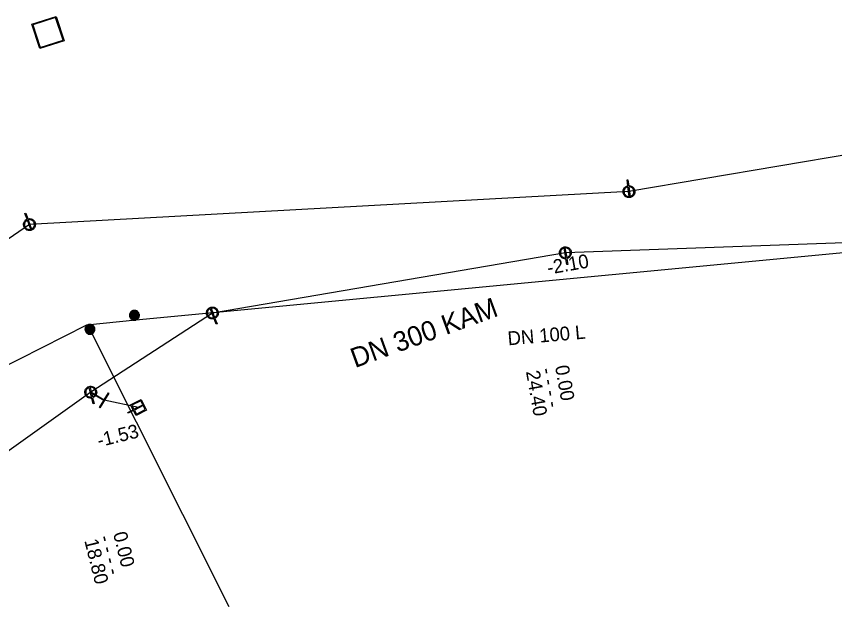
# Model space of a CAD drawing. Extents: x -818321 to -817653, y -1049725 to -1049329.
# Drawn here: x -817798.86 to -817757.35, y -1049402.58 to -1049372.62 of the extents above; entities that cross this region are included whole.
import ezdxf

# ---------------------------------------------------------------- set-up
doc = ezdxf.new("R2010")
doc.units = 0
doc.layers.add('Default', color=7, linetype='Continuous')
doc.layers.add('Level 0', color=7, linetype='Continuous')

msp = doc.modelspace()

# ---------------------------------------------------------------- linework, layer by layer
at = {"layer": 'Default'}
for points in [[(-817798.076, -1049373.026), (-817796.84, -1049372.624), (-817796.438, -1049373.86), (-817797.675, -1049374.262), (-817798.076, -1049373.026)], [(-817797.649, -1049374.211), (-817796.489, -1049373.834), (-817796.866, -1049372.675), (-817798.025, -1049373.052), (-817797.649, -1049374.211)], [(-817767.848, -1049381.223), (-817767.885, -1049380.925), (-817767.836, -1049380.919), (-817767.799, -1049381.217)], [(-817767.781, -1049381.767), (-817767.842, -1049381.274)], [(-817767.793, -1049381.268), (-817767.733, -1049381.761)], [(-817798.319, -1049382.917), (-817798.422, -1049382.635), (-817798.375, -1049382.618), (-817798.272, -1049382.9)], [(-817798.255, -1049382.948), (-817798.085, -1049383.415)], [(-817798.131, -1049383.432), (-817798.301, -1049382.965)], [(-817770.994, -1049384.872), (-817771.08, -1049384.382)], [(-817771.032, -1049384.373), (-817770.946, -1049384.863)], [(-817770.937, -1049384.913), (-817770.884, -1049385.209), (-817770.933, -1049385.218), (-817770.985, -1049384.922)], [(-817788.851, -1049387.918), (-817789.029, -1049387.453)], [(-817788.983, -1049387.436), (-817788.805, -1049387.9)], [(-817788.787, -1049387.948), (-817788.679, -1049388.228), (-817788.725, -1049388.246), (-817788.833, -1049387.965)], [(-817795.05, -1049391.944), (-817795.17, -1049391.461)], [(-817795.123, -1049391.449), (-817795.002, -1049391.932)], [(-817795.086, -1049391.706), (-817795.068, -1049391.696), (-817794.41, -1049392.091), (-817794.193, -1049391.727), (-817794.167, -1049391.743), (-817794.619, -1049392.496), (-817794.645, -1049392.48), (-817794.426, -1049392.116), (-817795.074, -1049391.728), (-817795.086, -1049391.706)], [(-817794.99, -1049391.982), (-817794.917, -1049392.273), (-817794.965, -1049392.285), (-817795.038, -1049391.993)], [(-817792.914, -1049392.629), (-817793.182, -1049392.765), (-817793.204, -1049392.721), (-817792.937, -1049392.585), (-817793.062, -1049392.34), (-817792.527, -1049392.067), (-817792.255, -1049392.602), (-817792.789, -1049392.874), (-817792.914, -1049392.629)], [(-817792.893, -1049392.563), (-817792.446, -1049392.335), (-817792.549, -1049392.134), (-817792.996, -1049392.361), (-817792.893, -1049392.563)], [(-817792.871, -1049392.607), (-817792.768, -1049392.808), (-817792.321, -1049392.581), (-817792.424, -1049392.379), (-817792.871, -1049392.607)]]:
    msp.add_lwpolyline(points, dxfattribs=at)
for points in [[(-817767.799, -1049381.217), (-817767.737, -1049381.213), (-817767.671, -1049381.241), (-817767.595, -1049381.271), (-817767.547, -1049381.337), (-817767.499, -1049381.403), (-817767.49, -1049381.481), (-817767.48, -1049381.559), (-817767.511, -1049381.635), (-817767.543, -1049381.711), (-817767.609, -1049381.759), (-817767.675, -1049381.806), (-817767.751, -1049381.815), (-817767.826, -1049381.824), (-817767.902, -1049381.795), (-817767.978, -1049381.765), (-817768.027, -1049381.698), (-817768.076, -1049381.632), (-817768.085, -1049381.554), (-817768.095, -1049381.476), (-817768.064, -1049381.401), (-817768.034, -1049381.325), (-817767.967, -1049381.277), (-817767.909, -1049381.235), (-817767.848, -1049381.223)], [(-817767.842, -1049381.274), (-817767.89, -1049381.283), (-817767.938, -1049381.318), (-817767.993, -1049381.358), (-817768.018, -1049381.42), (-817768.044, -1049381.483), (-817768.036, -1049381.548), (-817768.028, -1049381.612), (-817767.987, -1049381.668), (-817767.946, -1049381.723), (-817767.883, -1049381.748), (-817767.829, -1049381.769), (-817767.781, -1049381.767)], [(-817767.733, -1049381.761), (-817767.686, -1049381.751), (-817767.638, -1049381.718), (-817767.583, -1049381.679), (-817767.557, -1049381.615), (-817767.531, -1049381.551), (-817767.539, -1049381.487), (-817767.547, -1049381.422), (-817767.587, -1049381.367), (-817767.627, -1049381.313), (-817767.69, -1049381.287), (-817767.744, -1049381.265), (-817767.793, -1049381.268)], [(-817798.272, -1049382.9), (-817798.213, -1049382.883), (-817798.142, -1049382.894), (-817798.061, -1049382.907), (-817798, -1049382.96), (-817797.938, -1049383.014), (-817797.911, -1049383.087), (-817797.884, -1049383.161), (-817797.898, -1049383.243), (-817797.911, -1049383.324), (-817797.965, -1049383.385), (-817798.019, -1049383.446), (-817798.091, -1049383.472), (-817798.162, -1049383.498), (-817798.242, -1049383.486), (-817798.323, -1049383.474), (-817798.386, -1049383.42), (-817798.448, -1049383.366), (-817798.475, -1049383.293), (-817798.502, -1049383.219), (-817798.489, -1049383.139), (-817798.476, -1049383.058), (-817798.423, -1049382.997), (-817798.376, -1049382.942), (-817798.319, -1049382.917)], [(-817798.085, -1049383.415), (-817798.042, -1049383.395), (-817798.003, -1049383.352), (-817797.958, -1049383.301), (-817797.947, -1049383.233), (-817797.936, -1049383.165), (-817797.958, -1049383.104), (-817797.98, -1049383.043), (-817798.031, -1049382.999), (-817798.083, -1049382.954), (-817798.15, -1049382.944), (-817798.208, -1049382.935), (-817798.255, -1049382.948)], [(-817798.301, -1049382.965), (-817798.346, -1049382.985), (-817798.385, -1049383.03), (-817798.429, -1049383.081), (-817798.44, -1049383.148), (-817798.451, -1049383.214), (-817798.428, -1049383.275), (-817798.406, -1049383.337), (-817798.354, -1049383.382), (-817798.302, -1049383.426), (-817798.234, -1049383.436), (-817798.177, -1049383.445), (-817798.131, -1049383.432)], [(-817770.985, -1049384.922), (-817771.047, -1049384.929), (-817771.115, -1049384.905), (-817771.192, -1049384.879), (-817771.243, -1049384.815), (-817771.295, -1049384.752), (-817771.308, -1049384.675), (-817771.322, -1049384.598), (-817771.295, -1049384.52), (-817771.267, -1049384.442), (-817771.204, -1049384.391), (-817771.14, -1049384.341), (-817771.065, -1049384.327), (-817770.991, -1049384.314), (-817770.913, -1049384.34), (-817770.836, -1049384.366), (-817770.783, -1049384.429), (-817770.731, -1049384.493), (-817770.717, -1049384.571), (-817770.704, -1049384.648), (-817770.73, -1049384.725), (-817770.757, -1049384.802), (-817770.821, -1049384.853), (-817770.876, -1049384.899), (-817770.937, -1049384.913)], [(-817771.08, -1049384.382), (-817771.126, -1049384.394), (-817771.172, -1049384.43), (-817771.226, -1049384.472), (-817771.248, -1049384.537), (-817771.271, -1049384.602), (-817771.259, -1049384.666), (-817771.248, -1049384.73), (-817771.205, -1049384.783), (-817771.163, -1049384.836), (-817771.098, -1049384.857), (-817771.043, -1049384.877), (-817770.994, -1049384.872)], [(-817770.946, -1049384.863), (-817770.898, -1049384.851), (-817770.852, -1049384.814), (-817770.799, -1049384.771), (-817770.777, -1049384.707), (-817770.755, -1049384.643), (-817770.767, -1049384.579), (-817770.778, -1049384.515), (-817770.821, -1049384.462), (-817770.865, -1049384.409), (-817770.929, -1049384.387), (-817770.984, -1049384.369), (-817771.032, -1049384.373)], [(-817788.833, -1049387.965), (-817788.892, -1049387.984), (-817788.963, -1049387.974), (-817789.044, -1049387.963), (-817789.106, -1049387.91), (-817789.169, -1049387.857), (-817789.197, -1049387.785), (-817789.225, -1049387.711), (-817789.213, -1049387.63), (-817789.201, -1049387.548), (-817789.148, -1049387.486), (-817789.095, -1049387.424), (-817789.024, -1049387.397), (-817788.954, -1049387.37), (-817788.873, -1049387.38), (-817788.792, -1049387.391), (-817788.729, -1049387.444), (-817788.665, -1049387.496), (-817788.637, -1049387.57), (-817788.609, -1049387.642), (-817788.62, -1049387.723), (-817788.631, -1049387.804), (-817788.684, -1049387.866), (-817788.73, -1049387.922), (-817788.787, -1049387.948)], [(-817789.029, -1049387.453), (-817789.072, -1049387.474), (-817789.11, -1049387.518), (-817789.154, -1049387.57), (-817789.164, -1049387.638), (-817789.174, -1049387.706), (-817789.15, -1049387.767), (-817789.127, -1049387.828), (-817789.075, -1049387.871), (-817789.023, -1049387.914), (-817788.956, -1049387.924), (-817788.898, -1049387.932), (-817788.851, -1049387.918)], [(-817788.805, -1049387.9), (-817788.76, -1049387.879), (-817788.722, -1049387.834), (-817788.679, -1049387.782), (-817788.669, -1049387.715), (-817788.66, -1049387.648), (-817788.683, -1049387.587), (-817788.707, -1049387.527), (-817788.76, -1049387.483), (-817788.813, -1049387.439), (-817788.88, -1049387.43), (-817788.937, -1049387.423), (-817788.983, -1049387.436)], [(-817792.872, -1049387.543), (-817792.809, -1049387.543), (-817792.749, -1049387.575), (-817792.689, -1049387.607), (-817792.655, -1049387.668), (-817792.621, -1049387.728), (-817792.621, -1049387.793), (-817792.621, -1049387.858), (-817792.654, -1049387.918), (-817792.687, -1049387.977), (-817792.747, -1049388.01), (-817792.806, -1049388.043), (-817792.872, -1049388.043), (-817792.936, -1049388.043), (-817792.996, -1049388.01), (-817793.055, -1049387.977), (-817793.088, -1049387.918), (-817793.121, -1049387.858), (-817793.121, -1049387.793), (-817793.121, -1049387.728), (-817793.088, -1049387.668), (-817793.054, -1049387.607), (-817792.995, -1049387.575), (-817792.935, -1049387.543), (-817792.872, -1049387.543)], [(-817792.872, -1049387.566), (-817792.929, -1049387.566), (-817792.983, -1049387.596), (-817793.037, -1049387.625), (-817793.068, -1049387.679), (-817793.098, -1049387.734), (-817793.098, -1049387.793), (-817793.098, -1049387.852), (-817793.068, -1049387.906), (-817793.038, -1049387.96), (-817792.984, -1049387.99), (-817792.93, -1049388.019), (-817792.872, -1049388.019), (-817792.813, -1049388.019), (-817792.758, -1049387.99), (-817792.704, -1049387.96), (-817792.675, -1049387.906), (-817792.645, -1049387.852), (-817792.645, -1049387.793), (-817792.645, -1049387.734), (-817792.676, -1049387.679), (-817792.706, -1049387.625), (-817792.76, -1049387.596), (-817792.814, -1049387.566), (-817792.872, -1049387.566)], [(-817792.872, -1049387.583), (-817792.819, -1049387.583), (-817792.769, -1049387.61), (-817792.719, -1049387.637), (-817792.69, -1049387.688), (-817792.662, -1049387.738), (-817792.662, -1049387.793), (-817792.662, -1049387.848), (-817792.689, -1049387.897), (-817792.717, -1049387.947), (-817792.767, -1049387.975), (-817792.817, -1049388.002), (-817792.872, -1049388.002), (-817792.926, -1049388.002), (-817792.976, -1049387.975), (-817793.026, -1049387.947), (-817793.053, -1049387.897), (-817793.081, -1049387.848), (-817793.081, -1049387.793), (-817793.081, -1049387.738), (-817793.053, -1049387.688), (-817793.025, -1049387.637), (-817792.975, -1049387.61), (-817792.924, -1049387.583), (-817792.872, -1049387.583)], [(-817792.872, -1049387.605), (-817792.95, -1049387.605), (-817793.004, -1049387.66), (-817793.059, -1049387.715), (-817793.059, -1049387.793), (-817793.059, -1049387.871), (-817793.004, -1049387.926), (-817792.949, -1049387.98), (-817792.872, -1049387.98), (-817792.794, -1049387.98), (-817792.739, -1049387.926), (-817792.684, -1049387.871), (-817792.684, -1049387.793), (-817792.684, -1049387.715), (-817792.738, -1049387.66), (-817792.793, -1049387.605), (-817792.872, -1049387.605)], [(-817792.872, -1049387.628), (-817792.803, -1049387.628), (-817792.756, -1049387.676), (-817792.708, -1049387.724), (-817792.708, -1049387.792), (-817792.708, -1049387.861), (-817792.756, -1049387.909), (-817792.804, -1049387.957), (-817792.872, -1049387.957), (-817792.94, -1049387.957), (-817792.988, -1049387.909), (-817793.036, -1049387.861), (-817793.036, -1049387.792), (-817793.036, -1049387.724), (-817792.988, -1049387.676), (-817792.94, -1049387.628), (-817792.872, -1049387.628)], [(-817792.872, -1049387.648), (-817792.932, -1049387.648), (-817792.974, -1049387.69), (-817793.016, -1049387.733), (-817793.016, -1049387.792), (-817793.016, -1049387.852), (-817792.974, -1049387.894), (-817792.932, -1049387.937), (-817792.872, -1049387.937), (-817792.812, -1049387.937), (-817792.77, -1049387.894), (-817792.728, -1049387.852), (-817792.728, -1049387.792), (-817792.728, -1049387.733), (-817792.77, -1049387.69), (-817792.812, -1049387.648), (-817792.872, -1049387.648)], [(-817792.872, -1049387.668), (-817792.819, -1049387.668), (-817792.783, -1049387.705), (-817792.746, -1049387.741), (-817792.746, -1049387.793), (-817792.746, -1049387.845), (-817792.783, -1049387.881), (-817792.82, -1049387.918), (-817792.872, -1049387.918), (-817792.923, -1049387.918), (-817792.96, -1049387.881), (-817792.996, -1049387.845), (-817792.996, -1049387.793), (-817792.996, -1049387.741), (-817792.96, -1049387.705), (-817792.924, -1049387.668), (-817792.872, -1049387.668)], [(-817792.872, -1049387.691), (-817792.914, -1049387.691), (-817792.944, -1049387.721), (-817792.973, -1049387.75), (-817792.973, -1049387.793), (-817792.973, -1049387.835), (-817792.944, -1049387.865), (-817792.914, -1049387.894), (-817792.872, -1049387.894), (-817792.83, -1049387.894), (-817792.8, -1049387.865), (-817792.77, -1049387.835), (-817792.77, -1049387.793), (-817792.77, -1049387.75), (-817792.8, -1049387.721), (-817792.829, -1049387.691), (-817792.872, -1049387.691)], [(-817792.872, -1049387.708), (-817792.836, -1049387.708), (-817792.812, -1049387.733), (-817792.787, -1049387.758), (-817792.787, -1049387.793), (-817792.787, -1049387.828), (-817792.812, -1049387.852), (-817792.837, -1049387.877), (-817792.872, -1049387.877), (-817792.907, -1049387.877), (-817792.931, -1049387.852), (-817792.956, -1049387.828), (-817792.956, -1049387.793), (-817792.956, -1049387.758), (-817792.931, -1049387.733), (-817792.907, -1049387.708), (-817792.872, -1049387.708)], [(-817792.872, -1049387.73), (-817792.897, -1049387.73), (-817792.916, -1049387.749), (-817792.934, -1049387.767), (-817792.934, -1049387.793), (-817792.934, -1049387.819), (-817792.916, -1049387.837), (-817792.897, -1049387.855), (-817792.872, -1049387.855), (-817792.845, -1049387.855), (-817792.827, -1049387.837), (-817792.809, -1049387.819), (-817792.809, -1049387.793), (-817792.809, -1049387.767), (-817792.827, -1049387.749), (-817792.845, -1049387.73), (-817792.872, -1049387.73)], [(-817792.872, -1049387.754), (-817792.855, -1049387.754), (-817792.844, -1049387.765), (-817792.833, -1049387.776), (-817792.833, -1049387.793), (-817792.833, -1049387.809), (-817792.844, -1049387.821), (-817792.855, -1049387.832), (-817792.872, -1049387.832), (-817792.888, -1049387.832), (-817792.899, -1049387.821), (-817792.911, -1049387.809), (-817792.911, -1049387.793), (-817792.911, -1049387.776), (-817792.899, -1049387.765), (-817792.888, -1049387.754), (-817792.872, -1049387.754)], [(-817792.872, -1049387.769), (-817792.881, -1049387.769), (-817792.888, -1049387.776), (-817792.895, -1049387.783), (-817792.895, -1049387.793), (-817792.895, -1049387.803), (-817792.888, -1049387.81), (-817792.881, -1049387.816), (-817792.872, -1049387.816), (-817792.862, -1049387.816), (-817792.855, -1049387.81), (-817792.848, -1049387.803), (-817792.848, -1049387.793), (-817792.848, -1049387.783), (-817792.855, -1049387.776), (-817792.862, -1049387.769), (-817792.872, -1049387.769)], [(-817795.34, -1049388.64), (-817795.373, -1049388.587), (-817795.378, -1049388.519), (-817795.382, -1049388.451), (-817795.349, -1049388.391), (-817795.316, -1049388.33), (-817795.26, -1049388.295), (-817795.205, -1049388.261), (-817795.137, -1049388.257), (-817795.069, -1049388.254), (-817795.01, -1049388.287), (-817794.95, -1049388.32), (-817794.916, -1049388.375), (-817794.881, -1049388.43), (-817794.878, -1049388.498), (-817794.874, -1049388.566), (-817794.907, -1049388.625), (-817794.94, -1049388.685), (-817794.995, -1049388.719), (-817795.051, -1049388.754), (-817795.12, -1049388.757), (-817795.188, -1049388.761), (-817795.247, -1049388.727), (-817795.306, -1049388.694), (-817795.34, -1049388.64)], [(-817795.32, -1049388.628), (-817795.29, -1049388.676), (-817795.236, -1049388.707), (-817795.183, -1049388.737), (-817795.12, -1049388.734), (-817795.058, -1049388.731), (-817795.008, -1049388.699), (-817794.958, -1049388.668), (-817794.928, -1049388.614), (-817794.898, -1049388.561), (-817794.901, -1049388.499), (-817794.905, -1049388.437), (-817794.936, -1049388.388), (-817794.967, -1049388.337), (-817795.021, -1049388.307), (-817795.075, -1049388.277), (-817795.136, -1049388.281), (-817795.198, -1049388.284), (-817795.248, -1049388.315), (-817795.298, -1049388.347), (-817795.328, -1049388.402), (-817795.358, -1049388.457), (-817795.354, -1049388.518), (-817795.35, -1049388.579), (-817795.32, -1049388.628)], [(-817795.305, -1049388.619), (-817795.334, -1049388.574), (-817795.337, -1049388.517), (-817795.341, -1049388.46), (-817795.313, -1049388.41), (-817795.285, -1049388.359), (-817795.239, -1049388.33), (-817795.193, -1049388.301), (-817795.136, -1049388.298), (-817795.079, -1049388.295), (-817795.029, -1049388.322), (-817794.979, -1049388.35), (-817794.95, -1049388.397), (-817794.921, -1049388.443), (-817794.918, -1049388.5), (-817794.915, -1049388.557), (-817794.943, -1049388.606), (-817794.971, -1049388.656), (-817795.017, -1049388.685), (-817795.063, -1049388.714), (-817795.121, -1049388.717), (-817795.179, -1049388.72), (-817795.228, -1049388.692), (-817795.277, -1049388.663), (-817795.305, -1049388.619)], [(-817795.287, -1049388.607), (-817795.245, -1049388.673), (-817795.17, -1049388.691), (-817795.094, -1049388.708), (-817795.028, -1049388.666), (-817794.963, -1049388.625), (-817794.945, -1049388.55), (-817794.928, -1049388.474), (-817794.969, -1049388.408), (-817795.01, -1049388.342), (-817795.086, -1049388.325), (-817795.161, -1049388.307), (-817795.227, -1049388.348), (-817795.293, -1049388.39), (-817795.311, -1049388.465), (-817795.328, -1049388.54), (-817795.287, -1049388.607)], [(-817795.267, -1049388.595), (-817795.304, -1049388.537), (-817795.288, -1049388.471), (-817795.273, -1049388.405), (-817795.215, -1049388.369), (-817795.157, -1049388.333), (-817795.091, -1049388.348), (-817795.025, -1049388.363), (-817794.989, -1049388.421), (-817794.953, -1049388.479), (-817794.968, -1049388.545), (-817794.983, -1049388.611), (-817795.041, -1049388.647), (-817795.099, -1049388.683), (-817795.165, -1049388.668), (-817795.231, -1049388.653), (-817795.267, -1049388.595)], [(-817795.25, -1049388.585), (-817795.219, -1049388.636), (-817795.16, -1049388.649), (-817795.102, -1049388.662), (-817795.052, -1049388.63), (-817795.001, -1049388.599), (-817794.987, -1049388.541), (-817794.974, -1049388.483), (-817795.006, -1049388.432), (-817795.037, -1049388.381), (-817795.096, -1049388.367), (-817795.154, -1049388.354), (-817795.205, -1049388.386), (-817795.255, -1049388.417), (-817795.269, -1049388.475), (-817795.282, -1049388.533), (-817795.25, -1049388.585)], [(-817795.234, -1049388.574), (-817795.262, -1049388.529), (-817795.25, -1049388.479), (-817795.238, -1049388.429), (-817795.194, -1049388.401), (-817795.15, -1049388.374), (-817795.1, -1049388.386), (-817795.049, -1049388.397), (-817795.022, -1049388.441), (-817794.994, -1049388.485), (-817795.006, -1049388.535), (-817795.018, -1049388.586), (-817795.061, -1049388.613), (-817795.106, -1049388.641), (-817795.156, -1049388.63), (-817795.206, -1049388.618), (-817795.234, -1049388.574)], [(-817795.214, -1049388.562), (-817795.192, -1049388.597), (-817795.151, -1049388.607), (-817795.11, -1049388.616), (-817795.074, -1049388.594), (-817795.038, -1049388.572), (-817795.029, -1049388.531), (-817795.019, -1049388.49), (-817795.042, -1049388.454), (-817795.064, -1049388.418), (-817795.105, -1049388.409), (-817795.146, -1049388.399), (-817795.182, -1049388.422), (-817795.218, -1049388.444), (-817795.227, -1049388.485), (-817795.237, -1049388.526), (-817795.214, -1049388.562)], [(-817795.199, -1049388.552), (-817795.218, -1049388.523), (-817795.21, -1049388.489), (-817795.202, -1049388.455), (-817795.173, -1049388.436), (-817795.143, -1049388.418), (-817795.109, -1049388.426), (-817795.075, -1049388.434), (-817795.057, -1049388.463), (-817795.038, -1049388.493), (-817795.046, -1049388.527), (-817795.054, -1049388.561), (-817795.083, -1049388.579), (-817795.113, -1049388.598), (-817795.147, -1049388.59), (-817795.181, -1049388.582), (-817795.199, -1049388.552)], [(-817795.181, -1049388.541), (-817795.167, -1049388.563), (-817795.142, -1049388.568), (-817795.117, -1049388.574), (-817795.095, -1049388.56), (-817795.073, -1049388.547), (-817795.067, -1049388.521), (-817795.061, -1049388.496), (-817795.075, -1049388.475), (-817795.089, -1049388.452), (-817795.114, -1049388.447), (-817795.139, -1049388.441), (-817795.161, -1049388.454), (-817795.183, -1049388.468), (-817795.189, -1049388.493), (-817795.195, -1049388.518), (-817795.181, -1049388.541)], [(-817795.161, -1049388.528), (-817795.17, -1049388.514), (-817795.166, -1049388.499), (-817795.163, -1049388.483), (-817795.148, -1049388.475), (-817795.135, -1049388.466), (-817795.119, -1049388.469), (-817795.103, -1049388.473), (-817795.095, -1049388.487), (-817795.086, -1049388.501), (-817795.09, -1049388.516), (-817795.093, -1049388.532), (-817795.107, -1049388.541), (-817795.121, -1049388.55), (-817795.137, -1049388.546), (-817795.152, -1049388.542), (-817795.161, -1049388.528)], [(-817795.148, -1049388.52), (-817795.142, -1049388.528), (-817795.133, -1049388.531), (-817795.124, -1049388.533), (-817795.115, -1049388.528), (-817795.107, -1049388.522), (-817795.105, -1049388.513), (-817795.103, -1049388.504), (-817795.108, -1049388.495), (-817795.113, -1049388.487), (-817795.123, -1049388.485), (-817795.132, -1049388.483), (-817795.14, -1049388.488), (-817795.149, -1049388.493), (-817795.151, -1049388.502), (-817795.153, -1049388.512), (-817795.148, -1049388.52)], [(-817795.038, -1049391.993), (-817795.099, -1049392.004), (-817795.168, -1049391.986), (-817795.247, -1049391.965), (-817795.303, -1049391.905), (-817795.358, -1049391.845), (-817795.377, -1049391.77), (-817795.396, -1049391.693), (-817795.375, -1049391.614), (-817795.353, -1049391.534), (-817795.293, -1049391.479), (-817795.233, -1049391.424), (-817795.159, -1049391.406), (-817795.085, -1049391.388), (-817795.006, -1049391.408), (-817794.927, -1049391.428), (-817794.871, -1049391.488), (-817794.814, -1049391.548), (-817794.795, -1049391.624), (-817794.776, -1049391.7), (-817794.797, -1049391.779), (-817794.818, -1049391.858), (-817794.878, -1049391.913), (-817794.931, -1049391.962), (-817794.99, -1049391.982)], [(-817795.17, -1049391.461), (-817795.215, -1049391.477), (-817795.259, -1049391.516), (-817795.309, -1049391.562), (-817795.327, -1049391.628), (-817795.345, -1049391.694), (-817795.329, -1049391.757), (-817795.313, -1049391.821), (-817795.267, -1049391.87), (-817795.221, -1049391.92), (-817795.155, -1049391.937), (-817795.099, -1049391.952), (-817795.05, -1049391.944)], [(-817795.002, -1049391.932), (-817794.955, -1049391.917), (-817794.912, -1049391.876), (-817794.863, -1049391.83), (-817794.845, -1049391.765), (-817794.828, -1049391.7), (-817794.843, -1049391.636), (-817794.859, -1049391.573), (-817794.906, -1049391.523), (-817794.954, -1049391.473), (-817795.019, -1049391.456), (-817795.076, -1049391.442), (-817795.123, -1049391.449)]]:
    msp.add_open_spline(points, degree=3, dxfattribs=at)
at = {"layer": 'Level 0'}
for p, q in [((-817739.929, -1049376.803), (-817767.788, -1049381.512)), ((-817767.788, -1049381.512), (-817798.195, -1049383.185)), ((-817798.195, -1049383.185), (-817813.696, -1049393.785)), ((-817792.8, -1049388.031), (-817740.932, -1049383.074)), ((-817742.466, -1049383.589), (-817771.012, -1049384.628)), ((-817771.012, -1049384.628), (-817788.915, -1049387.682)), ((-817788.915, -1049387.682), (-817795.085, -1049391.702)), ((-817809.729, -1049395.603), (-817795.289, -1049388.269)), ((-817795.289, -1049388.269), (-817792.8, -1049388.031)), ((-817795.289, -1049388.269), (-817795.128, -1049388.508)), ((-817795.128, -1049388.508), (-817788.088, -1049402.578)), ((-817795.085, -1049391.702), (-817810.125, -1049402.424)), ((-817794.41, -1049392.104), (-817795.085, -1049391.702)), ((-817792.666, -1049392.477), (-817794.41, -1049392.104))]:
    msp.add_line(p, q, dxfattribs=at)

# ---------------------------------------------------------------- texts
for s, height, rotation, p in [('-2.10', 0.7, 10, (-817771.879, -1049385.733)), ('DN 300 KAM', 1, 20, (-817781.683, -1049390.476)), ('DN 100 L', 0.7, 5, (-817773.911, -1049389.32)), ('0.00', 0.7, 280, (-817771.538, -1049390.386)), ('24.40', 0.7, 280, (-817773.014, -1049390.652)), ('- - - -', 0.7, 280, (-817772.276, -1049390.519)), ('-1.53', 0.7, 14, (-817794.665, -1049394.494)), ('- - - -', 0.7, 284, (-817794.687, -1049399.047)), ('0.00', 0.7, 284, (-817793.959, -1049398.868)), ('18.80', 0.7, 284, (-817795.415, -1049399.226))]:
    msp.add_text(s, height=height, rotation=rotation, dxfattribs=at).set_placement(p)

doc.saveas('drawing.dxf')
